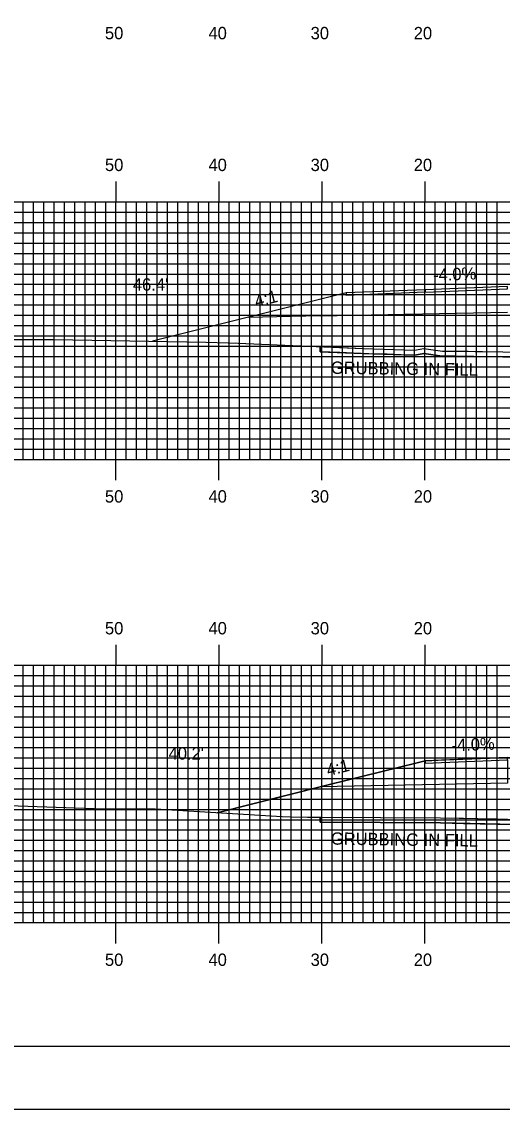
# Model space of a CAD drawing. Extents: x 1764546 to 1764889, y 442591 to 442811.
# Drawn here: x 1764652.2 to 1764698.8, y 442590.5 to 442696.2 of the extents above; entities that cross this region are included whole.
import ezdxf

# ---------------------------------------------------------------- set-up
doc = ezdxf.new("R2010")
doc.units = 0
for name, color, linetype in [('ANNOTATION', 7, 'Continuous'), ('BORDER', 7, 'Continuous'), ('D_Roadway_Centerline', 7, 'Continuous'), ('D_Roadway_Edge_Shoulder', 7, 'Continuous'), ('D_Roadway_SlopeLines', 7, 'Continuous'), ('D_Roadway_SubGrade', 7, 'Continuous'), ('D_Text_Standard', 7, 'Continuous'), ('GRUBBING IN FILL', 7, 'Continuous'), ('H_V ANNOTATION', 7, 'Continuous'), ('MAJOR', 7, 'Continuous'), ('MINOR', 7, 'Continuous'), ('PLOT BOUNDARY', 7, 'Continuous'), ('S_Roadway_Centerline', 7, 'Continuous')]:
    doc.layers.add(name, color=color, linetype=linetype)

msp = doc.modelspace()

# ---------------------------------------------------------------- linework, layer by layer
at = {"layer": 'ANNOTATION'}
for p, q in [((1764691.35, 442669.9), (1764683.7, 442669.59)), ((1764683.7, 442669.84), (1764683.7, 442669.59)), ((1764681.17, 442667.6), (1764699.34, 442667.97)), ((1764681.17, 442667.6), (1764674.18, 442667.46))]:
    msp.add_line(p, q, dxfattribs=at)
msp.add_lwpolyline([(1764691.35, 442670.15), (1764683.7, 442669.84), (1764664.9, 442665.14)], dxfattribs=at)
at = {"layer": 'BORDER'}
msp.add_lwpolyline([(1764561.74, 442596.67), (1764881.74, 442596.67), (1764881.74, 442806.67), (1764561.74, 442806.67)], close=True, dxfattribs=at)
at = {"layer": 'D_Roadway_Centerline'}
msp.add_lwpolyline([(1764671.18, 442619.35), (1764675.92, 442620.54), (1764681.17, 442621.85), (1764681.18, 442621.85), (1764689.31, 442623.89), (1764691.35, 442624.4), (1764691.35, 442624.4), (1764693.28, 442624.47), (1764699.34, 442624.72), (1764699.34, 442624.72), (1764711.34, 442624.96), (1764722.68, 442624.73), (1764723.34, 442624.72), (1764731.34, 442624.4), (1764741.52, 442621.85), (1764741.52, 442621.85), (1764743.35, 442621.4), (1764749.46, 442619.87), (1764756.1, 442618.21)], dxfattribs=at)
at = {"layer": 'D_Roadway_Edge_Shoulder'}
for points in [[(1764699.34, 442670.47), (1764691.35, 442670.15), (1764691.35, 442669.9), (1764699.34, 442670.22)], [(1764699.34, 442624.72), (1764691.35, 442624.4), (1764691.35, 442624.15), (1764699.34, 442624.47)]]:
    msp.add_lwpolyline(points, close=True, dxfattribs=at)
at = {"layer": 'D_Roadway_SlopeLines'}
msp.add_lwpolyline([(1764691.35, 442624.4), (1764681.17, 442621.85), (1764671.18, 442619.35)], dxfattribs=at)
at = {"layer": 'D_Roadway_SubGrade'}
msp.add_lwpolyline([(1764691.35, 442624.15), (1764699.34, 442624.47), (1764699.34, 442624.05), (1764699.34, 442622.22), (1764681.17, 442621.85), (1764691.35, 442624.4)], close=True, dxfattribs=at)
at = {"layer": 'GRUBBING IN FILL'}
for p, q in [((1764681.17, 442664.62), (1764681.17, 442664.12)), ((1764681.17, 442618.92), (1764681.17, 442618.42))]:
    msp.add_line(p, q, dxfattribs=at)
for points in [[(1764700.88, 442663.58), (1764697.91, 442663.63), (1764694.27, 442663.68), (1764693, 442663.68), (1764691.23, 442663.94), (1764690.36, 442663.79), (1764689.03, 442663.83), (1764687.68, 442663.87), (1764685.89, 442663.92), (1764684.39, 442663.98), (1764683.06, 442664.04), (1764681.17, 442664.12), (1764681.17, 442664.62), (1764685.31, 442664.44), (1764690.33, 442664.29), (1764691.22, 442664.44), (1764693.04, 442664.18), (1764694.29, 442664.18), (1764696.23, 442664.16), (1764698.91, 442664.12)], [(1764700.88, 442663.58), (1764697.91, 442663.63), (1764694.27, 442663.68), (1764693, 442663.68), (1764691.23, 442663.94), (1764690.36, 442663.79), (1764689.03, 442663.83), (1764687.68, 442663.87), (1764685.89, 442663.92), (1764684.39, 442663.98), (1764683.06, 442664.04), (1764681.17, 442664.12), (1764681.17, 442664.62), (1764685.31, 442664.44), (1764690.33, 442664.29), (1764691.22, 442664.44), (1764693.04, 442664.18), (1764694.29, 442664.18), (1764696.23, 442664.16), (1764698.91, 442664.12)], [(1764681.17, 442664.12), (1764685.29, 442663.94), (1764690.36, 442663.79), (1764691.23, 442663.94), (1764693, 442663.68), (1764695.53, 442663.67), (1764696.92, 442663.65), (1764698.9, 442663.62), (1764702.85, 442663.55), (1764707.64, 442663.59), (1764708.26, 442663.58), (1764710.77, 442663.67), (1764721.72, 442664.02), (1764726.7, 442663.99), (1764734.7, 442663.98), (1764741.52, 442663.99)], [(1764681.17, 442618.42), (1764692.84, 442618.36), (1764695.07, 442618.31), (1764701.49, 442618.17), (1764704.16, 442618.17), (1764705.07, 442618.09), (1764712.16, 442618.26), (1764712.83, 442618.24), (1764720.89, 442618.35), (1764726.89, 442618.46), (1764731.25, 442618.3), (1764732.55, 442618.27), (1764737.02, 442618.15), (1764741.52, 442618.08)]]:
    msp.add_lwpolyline(points, dxfattribs=at)
msp.add_lwpolyline([(1764681.17, 442618.92), (1764687.04, 442618.89), (1764692.84, 442618.86), (1764698.28, 442618.74), (1764701.49, 442618.67), (1764704.18, 442618.67), (1764704.64, 442618.63), (1764705.09, 442618.59), (1764708.62, 442618.68), (1764711.34, 442618.74), (1764711.34, 442618.24), (1764708.61, 442618.18), (1764705.07, 442618.09), (1764704.16, 442618.17), (1764701.49, 442618.17), (1764692.84, 442618.36), (1764681.17, 442618.42)], close=True, dxfattribs=at)
msp.add_lwpolyline([(1764681.17, 442618.92), (1764687.04, 442618.89), (1764692.84, 442618.86), (1764698.28, 442618.74), (1764701.49, 442618.67), (1764704.18, 442618.67), (1764704.64, 442618.63), (1764705.09, 442618.59), (1764708.62, 442618.68), (1764711.34, 442618.74), (1764711.34, 442618.24), (1764708.61, 442618.18), (1764705.07, 442618.09), (1764704.16, 442618.17), (1764701.49, 442618.17), (1764692.84, 442618.36), (1764681.17, 442618.42)], close=True, dxfattribs=at)
at = {"layer": 'MAJOR'}
for p, q in [((1764661.34, 442680.67), (1764661.34, 442678.67)), ((1764671.34, 442680.67), (1764671.34, 442678.67)), ((1764681.34, 442680.67), (1764681.34, 442678.67)), ((1764691.34, 442680.67), (1764691.34, 442678.67)), ((1764571.34, 442678.67), (1764851.34, 442678.67)), ((1764571.34, 442678.67), (1764851.34, 442678.67)), ((1764661.34, 442653.67), (1764661.34, 442678.67)), ((1764671.34, 442653.67), (1764671.34, 442678.67)), ((1764681.34, 442653.67), (1764681.34, 442678.67)), ((1764691.34, 442653.67), (1764691.34, 442678.67)), ((1764571.34, 442673.67), (1764851.34, 442673.67)), ((1764571.34, 442668.67), (1764851.34, 442668.67)), ((1764571.34, 442663.67), (1764851.34, 442663.67)), ((1764571.34, 442658.67), (1764851.34, 442658.67)), ((1764571.34, 442653.67), (1764851.34, 442653.67)), ((1764571.34, 442653.67), (1764851.34, 442653.67)), ((1764661.34, 442651.66), (1764661.34, 442653.67)), ((1764671.34, 442651.66), (1764671.34, 442653.67)), ((1764681.34, 442651.66), (1764681.34, 442653.67)), ((1764691.34, 442651.66), (1764691.34, 442653.67)), ((1764661.34, 442635.67), (1764661.34, 442633.67)), ((1764671.34, 442635.67), (1764671.34, 442633.67)), ((1764681.34, 442635.67), (1764681.34, 442633.67)), ((1764691.34, 442635.67), (1764691.34, 442633.67)), ((1764571.34, 442633.67), (1764851.34, 442633.67)), ((1764571.34, 442633.67), (1764851.34, 442633.67)), ((1764661.34, 442608.67), (1764661.34, 442633.67)), ((1764671.34, 442608.67), (1764671.34, 442633.67)), ((1764681.34, 442608.67), (1764681.34, 442633.67)), ((1764691.34, 442608.67), (1764691.34, 442633.67)), ((1764571.34, 442628.67), (1764851.34, 442628.67)), ((1764571.34, 442623.67), (1764851.34, 442623.67)), ((1764571.34, 442618.67), (1764851.34, 442618.67)), ((1764571.34, 442613.67), (1764851.34, 442613.67)), ((1764571.34, 442608.67), (1764851.34, 442608.67)), ((1764571.34, 442608.67), (1764851.34, 442608.67)), ((1764661.34, 442606.66), (1764661.34, 442608.67)), ((1764671.34, 442606.66), (1764671.34, 442608.67)), ((1764681.34, 442606.66), (1764681.34, 442608.67)), ((1764691.34, 442606.66), (1764691.34, 442608.67))]:
    msp.add_line(p, q, dxfattribs=at)
at = {"layer": 'MINOR'}
for p, q in [((1764652.34, 442653.67), (1764652.34, 442678.67)), ((1764653.34, 442653.67), (1764653.34, 442678.67)), ((1764654.34, 442653.67), (1764654.34, 442678.67)), ((1764655.34, 442653.67), (1764655.34, 442678.67)), ((1764656.34, 442653.67), (1764656.34, 442678.67)), ((1764657.34, 442653.67), (1764657.34, 442678.67)), ((1764658.34, 442653.67), (1764658.34, 442678.67)), ((1764659.34, 442653.67), (1764659.34, 442678.67)), ((1764660.34, 442653.67), (1764660.34, 442678.67)), ((1764662.34, 442653.67), (1764662.34, 442678.67)), ((1764663.34, 442653.67), (1764663.34, 442678.67)), ((1764664.34, 442653.67), (1764664.34, 442678.67)), ((1764665.34, 442653.67), (1764665.34, 442678.67)), ((1764666.34, 442653.67), (1764666.34, 442678.67)), ((1764667.34, 442653.67), (1764667.34, 442678.67)), ((1764668.34, 442653.67), (1764668.34, 442678.67)), ((1764669.34, 442653.67), (1764669.34, 442678.67)), ((1764670.34, 442653.67), (1764670.34, 442678.67)), ((1764672.34, 442653.67), (1764672.34, 442678.67)), ((1764673.34, 442653.67), (1764673.34, 442678.67)), ((1764674.34, 442653.67), (1764674.34, 442678.67)), ((1764675.34, 442653.67), (1764675.34, 442678.67)), ((1764676.34, 442653.67), (1764676.34, 442678.67)), ((1764677.34, 442653.67), (1764677.34, 442678.67)), ((1764678.34, 442653.67), (1764678.34, 442678.67)), ((1764679.34, 442653.67), (1764679.34, 442678.67)), ((1764680.34, 442653.67), (1764680.34, 442678.67)), ((1764682.34, 442653.67), (1764682.34, 442678.67)), ((1764683.34, 442653.67), (1764683.34, 442678.67)), ((1764684.34, 442653.67), (1764684.34, 442678.67)), ((1764685.34, 442653.67), (1764685.34, 442678.67)), ((1764686.34, 442653.67), (1764686.34, 442678.67)), ((1764687.34, 442653.67), (1764687.34, 442678.67)), ((1764688.34, 442653.67), (1764688.34, 442678.67)), ((1764689.34, 442653.67), (1764689.34, 442678.67)), ((1764690.34, 442653.67), (1764690.34, 442678.67)), ((1764692.34, 442653.67), (1764692.34, 442678.67)), ((1764693.34, 442653.67), (1764693.34, 442678.67)), ((1764694.34, 442653.67), (1764694.34, 442678.67)), ((1764695.34, 442653.67), (1764695.34, 442678.67)), ((1764696.34, 442653.67), (1764696.34, 442678.67)), ((1764697.34, 442653.67), (1764697.34, 442678.67)), ((1764698.34, 442653.67), (1764698.34, 442678.67)), ((1764571.34, 442677.67), (1764851.34, 442677.67)), ((1764571.34, 442676.67), (1764851.34, 442676.67)), ((1764571.34, 442675.67), (1764851.34, 442675.67)), ((1764571.34, 442674.67), (1764851.34, 442674.67)), ((1764571.34, 442672.67), (1764851.34, 442672.67)), ((1764571.34, 442671.67), (1764851.34, 442671.67)), ((1764571.34, 442670.67), (1764851.34, 442670.67)), ((1764571.34, 442669.67), (1764851.34, 442669.67)), ((1764571.34, 442667.67), (1764851.34, 442667.67)), ((1764571.34, 442666.67), (1764851.34, 442666.67)), ((1764571.34, 442665.67), (1764851.34, 442665.67)), ((1764571.34, 442664.67), (1764851.34, 442664.67)), ((1764571.34, 442662.67), (1764851.34, 442662.67)), ((1764571.34, 442661.67), (1764851.34, 442661.67)), ((1764571.34, 442660.67), (1764851.34, 442660.67)), ((1764571.34, 442659.67), (1764851.34, 442659.67)), ((1764571.34, 442657.67), (1764851.34, 442657.67)), ((1764571.34, 442656.67), (1764851.34, 442656.67)), ((1764571.34, 442655.67), (1764851.34, 442655.67)), ((1764571.34, 442654.67), (1764851.34, 442654.67)), ((1764652.34, 442608.67), (1764652.34, 442633.67)), ((1764653.34, 442608.67), (1764653.34, 442633.67)), ((1764654.34, 442608.67), (1764654.34, 442633.67)), ((1764655.34, 442608.67), (1764655.34, 442633.67)), ((1764656.34, 442608.67), (1764656.34, 442633.67)), ((1764657.34, 442608.67), (1764657.34, 442633.67)), ((1764658.34, 442608.67), (1764658.34, 442633.67)), ((1764659.34, 442608.67), (1764659.34, 442633.67)), ((1764660.34, 442608.67), (1764660.34, 442633.67)), ((1764662.34, 442608.67), (1764662.34, 442633.67)), ((1764663.34, 442608.67), (1764663.34, 442633.67)), ((1764664.34, 442608.67), (1764664.34, 442633.67)), ((1764665.34, 442608.67), (1764665.34, 442633.67)), ((1764666.34, 442608.67), (1764666.34, 442633.67)), ((1764667.34, 442608.67), (1764667.34, 442633.67)), ((1764668.34, 442608.67), (1764668.34, 442633.67)), ((1764669.34, 442608.67), (1764669.34, 442633.67)), ((1764670.34, 442608.67), (1764670.34, 442633.67)), ((1764672.34, 442608.67), (1764672.34, 442633.67)), ((1764673.34, 442608.67), (1764673.34, 442633.67)), ((1764674.34, 442608.67), (1764674.34, 442633.67)), ((1764675.34, 442608.67), (1764675.34, 442633.67)), ((1764676.34, 442608.67), (1764676.34, 442633.67)), ((1764677.34, 442608.67), (1764677.34, 442633.67)), ((1764678.34, 442608.67), (1764678.34, 442633.67)), ((1764679.34, 442608.67), (1764679.34, 442633.67)), ((1764680.34, 442608.67), (1764680.34, 442633.67)), ((1764682.34, 442608.67), (1764682.34, 442633.67)), ((1764683.34, 442608.67), (1764683.34, 442633.67)), ((1764684.34, 442608.67), (1764684.34, 442633.67)), ((1764685.34, 442608.67), (1764685.34, 442633.67)), ((1764686.34, 442608.67), (1764686.34, 442633.67)), ((1764687.34, 442608.67), (1764687.34, 442633.67)), ((1764688.34, 442608.67), (1764688.34, 442633.67)), ((1764689.34, 442608.67), (1764689.34, 442633.67)), ((1764690.34, 442608.67), (1764690.34, 442633.67)), ((1764692.34, 442608.67), (1764692.34, 442633.67)), ((1764693.34, 442608.67), (1764693.34, 442633.67)), ((1764694.34, 442608.67), (1764694.34, 442633.67)), ((1764695.34, 442608.67), (1764695.34, 442633.67)), ((1764696.34, 442608.67), (1764696.34, 442633.67)), ((1764697.34, 442608.67), (1764697.34, 442633.67)), ((1764698.34, 442608.67), (1764698.34, 442633.67)), ((1764571.34, 442632.67), (1764851.34, 442632.67)), ((1764571.34, 442631.67), (1764851.34, 442631.67)), ((1764571.34, 442630.67), (1764851.34, 442630.67)), ((1764571.34, 442629.67), (1764851.34, 442629.67)), ((1764571.34, 442627.67), (1764851.34, 442627.67)), ((1764571.34, 442626.67), (1764851.34, 442626.67)), ((1764571.34, 442625.67), (1764851.34, 442625.67)), ((1764571.34, 442624.67), (1764851.34, 442624.67)), ((1764571.34, 442622.67), (1764851.34, 442622.67)), ((1764571.34, 442621.67), (1764851.34, 442621.67)), ((1764571.34, 442620.67), (1764851.34, 442620.67)), ((1764571.34, 442619.67), (1764851.34, 442619.67)), ((1764571.34, 442617.67), (1764851.34, 442617.67)), ((1764571.34, 442616.67), (1764851.34, 442616.67)), ((1764571.34, 442615.67), (1764851.34, 442615.67)), ((1764571.34, 442614.67), (1764851.34, 442614.67)), ((1764571.34, 442612.67), (1764851.34, 442612.67)), ((1764571.34, 442611.67), (1764851.34, 442611.67)), ((1764571.34, 442610.67), (1764851.34, 442610.67)), ((1764571.34, 442609.67), (1764851.34, 442609.67))]:
    msp.add_line(p, q, dxfattribs=at)
at = {"layer": 'PLOT BOUNDARY'}
msp.add_lwpolyline([(1764545.56, 442590.55), (1764885.56, 442590.55), (1764885.56, 442810.55), (1764545.56, 442810.55)], close=True, dxfattribs=at)
at = {"layer": 'S_Roadway_Centerline'}
for points in [[(1764643.4, 442665.32), (1764655.3, 442665.32), (1764670.07, 442665.05), (1764672.24, 442664.98), (1764673.22, 442664.96), (1764685.31, 442664.44), (1764690.33, 442664.29), (1764691.22, 442664.44), (1764693.04, 442664.18), (1764695.53, 442664.17), (1764696.93, 442664.15), (1764698.91, 442664.12), (1764702.85, 442664.05), (1764707.64, 442664.09), (1764708.25, 442664.08), (1764710.75, 442664.17), (1764721.71, 442664.52), (1764726.7, 442664.49), (1764734.7, 442664.48), (1764744.5, 442664.49), (1764752.58, 442664.4), (1764758.91, 442664.42)], [(1764643.54, 442620.32), (1764659.22, 442619.77), (1764665.13, 442619.71), (1764677.49, 442618.99), (1764678.3, 442618.94), (1764679.95, 442618.93), (1764681.25, 442618.92), (1764692.84, 442618.86), (1764695.08, 442618.81), (1764701.49, 442618.67), (1764704.18, 442618.67), (1764705.09, 442618.59), (1764712.16, 442618.76), (1764712.84, 442618.74), (1764720.88, 442618.85), (1764726.89, 442618.96), (1764731.26, 442618.8), (1764732.56, 442618.77), (1764737.03, 442618.65), (1764747.72, 442618.48), (1764752.4, 442618.2), (1764754.65, 442618.05), (1764760.02, 442618.64)]]:
    msp.add_lwpolyline(points, dxfattribs=at)

# ---------------------------------------------------------------- texts
at = {"layer": 'ANNOTATION'}
for s, rotation, p in [('-4.0%', 2.2909, (1764692.15, 442670.98)), ('4:1', 14.0377, (1764674.97, 442668.44)), ('-4.0%', 2.2906, (1764693.94, 442625.3)), ('4:1', 14.039, (1764681.94, 442622.89))]:
    msp.add_text(s, height=1.2, rotation=rotation, dxfattribs=at).set_placement(p)
at = {"layer": 'D_Text_Standard'}
for s, p in [("46.4'", (1764662.98, 442670.06)), ("40.2'", (1764666.45, 442624.51))]:
    msp.add_text(s, height=1.2, dxfattribs=at).set_placement(p)
at = {"layer": 'GRUBBING IN FILL'}
for p in [(1764682.2, 442661.98), (1764682.2, 442616.25)]:
    msp.add_text('GRUBBING IN FILL', height=1.2, rotation=359.1951, dxfattribs=at).set_placement(p)
at = {"layer": 'H_V ANNOTATION'}
for s, p in [('50', (1764660.27, 442694.47)), ('40', (1764670.32, 442694.47)), ('30', (1764680.24, 442694.47)), ('20', (1764690.25, 442694.47)), ('50', (1764660.27, 442681.67)), ('40', (1764670.32, 442681.67)), ('30', (1764680.24, 442681.67)), ('20', (1764690.25, 442681.67)), ('50', (1764660.27, 442649.47)), ('40', (1764670.32, 442649.47)), ('30', (1764680.24, 442649.47)), ('20', (1764690.25, 442649.47)), ('50', (1764660.27, 442636.67)), ('40', (1764670.32, 442636.67)), ('30', (1764680.24, 442636.67)), ('20', (1764690.25, 442636.67)), ('50', (1764660.27, 442604.47)), ('40', (1764670.32, 442604.47)), ('30', (1764680.24, 442604.47)), ('20', (1764690.25, 442604.47))]:
    msp.add_text(s, height=1.2, dxfattribs=at).set_placement(p)

doc.saveas('drawing.dxf')
